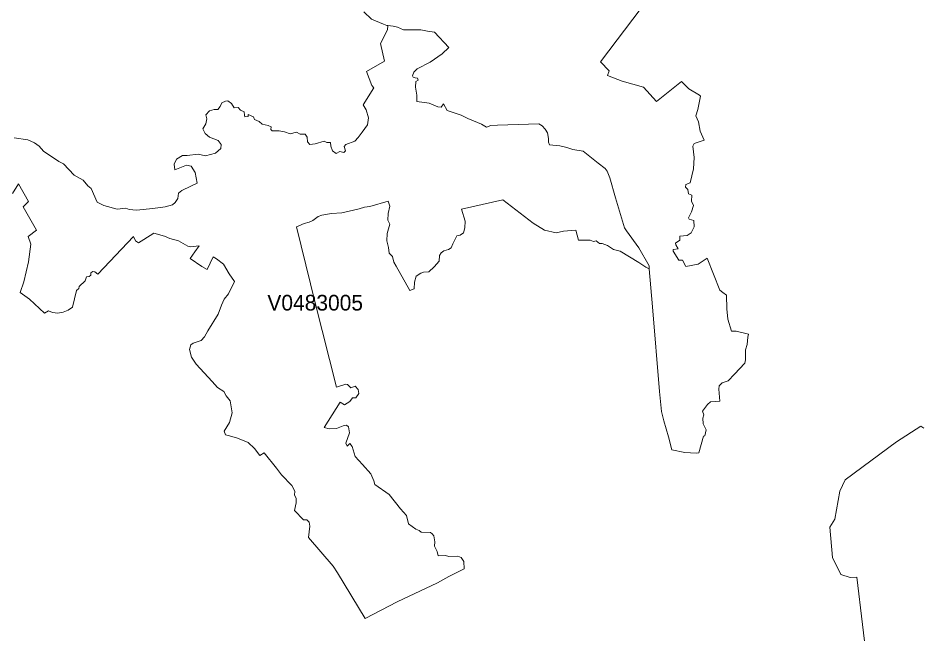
# Model space of a CAD drawing. Extents: x 369010 to 735936, y 6377141 to 6616555.
# Drawn here: x 393307 to 399077, y 6478465 to 6482389 of the extents above; entities that cross this region are included whole.
import ezdxf
from ezdxf.enums import TextEntityAlignment as Align

# ---------------------------------------------------------------- set-up
doc = ezdxf.new("R2010")
doc.units = 0
doc.header["$LTSCALE"] = 40
doc.layers.add('3', color=7, linetype='Continuous', lineweight=13)
doc.layers.add('4', color=7, linetype='Continuous')

msp = doc.modelspace()

# ---------------------------------------------------------------- linework, layer by layer
at = {"layer": '3'}
for points in [[(394667.46, 6481843.62), (394684.68, 6481817.3), (394710.66, 6481818.63), (394726.38, 6481802.9), (394748.73, 6481790.99), (394751.37, 6481771.29), (394754.02, 6481759.37), (394775.04, 6481760.7), (394773.72, 6481775.26), (394807.81, 6481759.37), (394814.43, 6481743.65), (394844.72, 6481730.41), (394864.41, 6481713.36), (394902.65, 6481704.1), (394921.02, 6481694.99), (394918.37, 6481679.11), (394927.64, 6481671.16), (394972.32, 6481669.84), (395006.42, 6481663.38), (395042, 6481651.47), (395082.55, 6481662.06), (395106.21, 6481650.14), (395137.83, 6481650.14), (395149.74, 6481630.45), (395152.23, 6481600.16), (395166.79, 6481583.11), (395202.21, 6481588.41), (395259.64, 6481605.46), (395275.53, 6481596.35), (395299.19, 6481596.35), (395301.84, 6481572.69), (395312.27, 6481543.72), (395334.61, 6481525.19), (395358.28, 6481539.75), (395384.59, 6481533.13), (395395.18, 6481543.72), (395385.92, 6481571.36), (395397.67, 6481583.11), (395454.27, 6481605.46), (395475.29, 6481627.96), (395501.6, 6481662.06), (395534.37, 6481709.23), (395542.15, 6481753.91), (395527.75, 6481803.9), (395514.51, 6481826.4), (395508.06, 6481835.51), (395575.09, 6481943.42), (395561.85, 6481959.3), (395529.08, 6482047.52), (395644.6, 6482114.05), (395618.28, 6482227.25), (395662.97, 6482314.14), (395665.95, 6482341.45), (395658.67, 6482342.28), (395637.65, 6482349.73), (395561.52, 6482382.66), (395512.86, 6482428.67)], [(395512.86, 6482428.67), (395561.52, 6482382.66), (395637.65, 6482349.73), (395658.67, 6482342.28), (395665.95, 6482341.45)], [(397280.44, 6482453), (397021.76, 6482109.08), (397077.04, 6482052.48), (397065.12, 6482023.85), (397159.79, 6481986.94), (397295.34, 6481948.71), (397377.92, 6481857.35), (397536.97, 6481984.96), (397584.47, 6481938.95), (397652.82, 6481896.74), (397657.96, 6481891.61), (397640.91, 6481806.05), (397627.83, 6481765.17), (397644.88, 6481728.43), (397655.47, 6481669.18), (397682.95, 6481611.25), (397617.24, 6481590.23), (397609.3, 6481572.36), (397618.57, 6481499.86), (397613.27, 6481428.86), (397593.57, 6481338), (397564.61, 6481328.9), (397561.96, 6481310.36), (397577.85, 6481297.29), (397583.15, 6481268.32), (397602.84, 6481260.38), (397600.19, 6481222.15), (397614.59, 6481195.01), (397601.35, 6481154.13), (397582.98, 6481116.06), (397585.63, 6481106.79), (397615.92, 6481098.85), (397617.24, 6481059.46), (397600.03, 6481021.23), (397573.88, 6481002.86), (397526.38, 6481000.21), (397526.55, 6480973.4), (397500.23, 6480953.54), (397501.55, 6480943.11), (397515.95, 6480919.44), (397484.34, 6480914.15), (397484.34, 6480903.55), (397521.25, 6480845.63), (397543.59, 6480845.63), (397563.29, 6480810.04), (397564.61, 6480804.91), (397643.56, 6480820.64), (397700.16, 6480858.87), (397782.58, 6480655.13), (397800.95, 6480639.41), (397824.62, 6480622.2), (397827.27, 6480536.8), (397833.89, 6480469.6), (397856.23, 6480394.63), (397886.52, 6480394.63), (397964.97, 6480374.27), (397959.67, 6480355.74), (397957.02, 6480309.73), (397945.27, 6480274.14), (397945.27, 6480210.92), (397941.3, 6480189.9), (397875.59, 6480118.9), (397834.88, 6480078.02), (397796.65, 6480064.94), (397778.28, 6480045.08), (397775.96, 6480024.73), (397781.26, 6479947.11), (397722.01, 6479943.13), (397703.8, 6479927.25), (397672.19, 6479884.05), (397678.81, 6479860.38), (397673.51, 6479839.36), (397674.84, 6479802.46), (397694.53, 6479764.22), (397685.26, 6479727.48), (397677.49, 6479724.83), (397647.2, 6479618.25), (397630.15, 6479615.6), (397558.98, 6479620.9), (397474.91, 6479636.62), (397454.05, 6479720.37), (397423.77, 6479821.65), (397410.69, 6479880.9), (397396.29, 6480010.33), (397352.93, 6480549.04)], [(397515.95, 6480919.44), (397501.55, 6480943.11), (397500.23, 6480953.54), (397526.55, 6480973.4), (397526.38, 6481000.21), (397573.88, 6481002.86), (397600.03, 6481021.23), (397617.24, 6481059.46), (397615.92, 6481098.85), (397585.63, 6481106.79), (397582.98, 6481116.06), (397601.35, 6481154.13), (397614.59, 6481195.01), (397600.19, 6481222.15), (397602.84, 6481260.38), (397583.15, 6481268.32), (397577.85, 6481297.29), (397561.96, 6481310.36), (397564.61, 6481328.9), (397593.57, 6481338), (397613.27, 6481428.86), (397618.57, 6481499.86), (397609.3, 6481572.36), (397617.24, 6481590.23), (397682.95, 6481611.25), (397655.47, 6481669.18), (397644.88, 6481728.43), (397627.83, 6481765.17), (397640.91, 6481806.05), (397657.96, 6481891.61), (397652.82, 6481896.74), (397584.47, 6481938.95), (397536.97, 6481984.96), (397377.92, 6481857.35), (397295.34, 6481948.71), (397159.79, 6481986.94), (397065.12, 6482023.85), (397077.04, 6482052.48), (397021.76, 6482109.08), (397280.44, 6482453)], [(395665.95, 6482341.45), (395662.97, 6482314.14), (395618.28, 6482227.25), (395644.6, 6482114.05), (395529.08, 6482047.52), (395561.85, 6481959.3), (395575.09, 6481943.42), (395508.06, 6481835.51), (395514.51, 6481826.4), (395527.75, 6481803.9), (395542.15, 6481753.91), (395534.37, 6481709.23), (395501.6, 6481662.06), (395475.29, 6481627.96), (395454.27, 6481605.46), (395397.67, 6481583.11), (395385.92, 6481571.36), (395395.18, 6481543.72), (395384.59, 6481533.13), (395358.28, 6481539.75), (395334.61, 6481525.19), (395312.27, 6481543.72), (395301.84, 6481572.69), (395299.19, 6481596.35), (395275.53, 6481596.35), (395259.64, 6481605.46), (395202.21, 6481588.41), (395166.79, 6481583.11), (395152.23, 6481600.16), (395149.74, 6481630.45), (395137.83, 6481650.14), (395106.21, 6481650.14), (395082.55, 6481662.06), (395042, 6481651.47), (395006.42, 6481663.38), (394972.32, 6481669.84), (394927.64, 6481671.16), (394918.37, 6481679.11), (394921.02, 6481694.99), (394902.65, 6481704.1), (394864.41, 6481713.36), (394844.72, 6481730.41), (394814.43, 6481743.65), (394807.81, 6481759.37), (394773.72, 6481775.26), (394775.04, 6481760.7), (394754.02, 6481759.37), (394751.37, 6481771.29), (394748.73, 6481790.99), (394726.38, 6481802.9), (394710.66, 6481818.63), (394684.68, 6481817.3), (394667.46, 6481843.62), (394643.8, 6481860.66), (394630.72, 6481859.34), (394607.05, 6481848.75), (394596.46, 6481826.4), (394580.74, 6481805.38), (394558.4, 6481805.38), (394528.11, 6481797.44), (394504.44, 6481772.45), (394511.06, 6481747.46), (394504.44, 6481714.52), (394486.07, 6481682.91), (394499.15, 6481654.11), (394526.95, 6481629.45), (394583.55, 6481608.44), (394601.92, 6481583.44), (394599.28, 6481558.45), (394566.34, 6481528.17), (394501.96, 6481511.12), (394454.63, 6481521.55), (394386.27, 6481513.77), (394355.99, 6481512.44), (394316.6, 6481490.1), (394303.36, 6481458.49), (394306, 6481422.91), (394380.98, 6481451.87), (394409.94, 6481445.25), (394436.25, 6481405.86), (394449.66, 6481336.51), (394408.95, 6481318.14), (394352.34, 6481290.5), (394330, 6481273.46), (394326.03, 6481239.2), (394308.98, 6481212.88), (394291.94, 6481198.32), (394245.93, 6481186.57), (394165.99, 6481175.97), (394063.37, 6481164.22), (394016.04, 6481169.35), (393995.02, 6481178.62), (393938.42, 6481170.68), (393853.35, 6481195.5), (393811.31, 6481216.52), (393773.41, 6481303.08), (393751.07, 6481320.13), (393722.11, 6481355.71), (393664.18, 6481387.32), (393597.15, 6481459.65)], [(395549.6, 6481188.22), (395666.61, 6481222.48), (395678.53, 6481190.87), (395667.94, 6481143.53), (395663.96, 6481101.5), (395677.2, 6481075.02), (395659.99, 6481015.93), (395657.51, 6480969.76), (395669.26, 6480927.72), (395673.23, 6480890.81), (395694.25, 6480869.79), (395703.52, 6480832.88), (395718.75, 6480807.89), (395805.47, 6480652.65), (395831.78, 6480664.4), (395834.43, 6480706.6), (395845.02, 6480744.67), (395875.31, 6480763.21), (395892.36, 6480769.66), (395926.62, 6480772.31), (395960.71, 6480803.92), (395992.32, 6480840.83), (395994.97, 6480874.92), (396005.4, 6480893.46), (396020.96, 6480904.88), (396052.57, 6480913.98), (396068.29, 6480924.57), (396078.88, 6480949.56), (396105.2, 6481000.87), (396126.22, 6481004.84), (396147.24, 6481020.73), (396156.34, 6481052.18), (396157.66, 6481094.38), (396133.99, 6481172), (396397.64, 6481231.58), (396592.28, 6481082.79), (396664.6, 6481036.78), (396739.08, 6481021.39), (396785.25, 6481030.5), (396862.71, 6481038.44), (396879.92, 6480973.89), (396954.73, 6480972.73), (396975.91, 6480964.79), (396992.96, 6480968.76), (397015.3, 6480951.55), (397031.03, 6480951.55), (397065.29, 6480939.8), (397104.68, 6480913.48), (397145.56, 6480904.22), (397265.71, 6480832.22), (397310.56, 6480800.78), (397332.24, 6480791.67), (397330.59, 6480810.87), (397265.21, 6480924.74), (397186.27, 6481033.97), (397174.35, 6481052.51), (397116.76, 6481244), (397079.85, 6481371.6), (397064.13, 6481412.48), (397050.89, 6481430.85), (397005.21, 6481464.78), (396910.54, 6481541.08), (396843.84, 6481551.34), (396807.1, 6481564.41), (396762.41, 6481575), (396695.38, 6481581.46), (396688.76, 6481597.35), (396688.76, 6481622.34), (396682.14, 6481657.92), (396667.75, 6481680.26), (396648.05, 6481701.28), (396628.19, 6481715.85), (396365.2, 6481706.58), (396322.34, 6481703.93), (396294.7, 6481694.66), (396263.09, 6481713.03), (396175.21, 6481748.29), (396133.17, 6481770.79), (396043.8, 6481800.92), (396020.13, 6481841.8), (396004.24, 6481822.1), (395983.22, 6481823.42), (395929.27, 6481845.77), (395850.49, 6481857.52), (395849.16, 6481897.07), (395841.22, 6481949.7), (395843.87, 6481985.29), (395858.27, 6481993.07), (395853.13, 6482004.98), (395839.89, 6482008.95), (395826.82, 6482011.6), (395821.36, 6482020.21), (395830.63, 6482045.2), (395851.64, 6482064.9), (395935.89, 6482108.42), (396010.86, 6482161.05), (396052.9, 6482201.77), (395962.2, 6482299.25), (395917.68, 6482305.37), (395874.32, 6482313.32)], [(395874.32, 6482313.32), (395823.01, 6482314.64), (395763.93, 6482313.32), (395725.7, 6482331.69), (395698.06, 6482338.31), (395665.95, 6482341.45)], [(395665.95, 6482341.45), (395698.06, 6482338.31), (395725.7, 6482331.69), (395763.93, 6482313.32), (395823.01, 6482314.64), (395874.32, 6482313.32), (395917.68, 6482305.37), (395962.2, 6482299.25), (396052.9, 6482201.77), (396010.86, 6482161.05), (395935.89, 6482108.42), (395851.64, 6482064.9), (395830.63, 6482045.2), (395821.36, 6482020.21), (395826.82, 6482011.6), (395839.89, 6482008.95), (395853.13, 6482004.98), (395858.27, 6481993.07), (395843.87, 6481985.29), (395841.22, 6481949.7), (395849.16, 6481897.07), (395850.49, 6481857.52), (395929.27, 6481845.77), (395983.22, 6481823.42), (396004.24, 6481822.1), (396020.13, 6481841.8), (396043.8, 6481800.92), (396133.17, 6481770.79), (396175.21, 6481748.29), (396263.09, 6481713.03), (396294.7, 6481694.66), (396322.34, 6481703.93), (396365.2, 6481706.58), (396628.19, 6481715.85), (396648.05, 6481701.28), (396667.75, 6481680.26), (396682.14, 6481657.92), (396688.76, 6481622.34), (396688.76, 6481597.35), (396695.38, 6481581.46), (396762.41, 6481575), (396807.1, 6481564.41), (396843.84, 6481551.34), (396910.54, 6481541.08), (397005.21, 6481464.78), (397050.89, 6481430.85), (397064.13, 6481412.48), (397079.85, 6481371.6), (397116.76, 6481244), (397174.35, 6481052.51), (397186.27, 6481033.97), (397265.21, 6480924.74), (397330.59, 6480810.87), (397332.24, 6480791.67), (397352.93, 6480549.04), (397396.29, 6480010.33), (397410.69, 6479880.9), (397423.77, 6479821.65), (397454.05, 6479720.37), (397474.91, 6479636.62), (397558.98, 6479620.9), (397630.15, 6479615.6), (397647.2, 6479618.25), (397677.49, 6479724.83), (397685.26, 6479727.48), (397694.53, 6479764.22), (397674.84, 6479802.46), (397673.51, 6479839.36), (397678.81, 6479860.38), (397672.19, 6479884.05), (397703.8, 6479927.25), (397722.01, 6479943.13), (397781.26, 6479947.11), (397775.96, 6480024.73), (397778.28, 6480045.08), (397796.65, 6480064.94), (397834.88, 6480078.02), (397875.59, 6480118.9), (397941.3, 6480189.9), (397945.27, 6480210.92), (397945.27, 6480274.14), (397957.02, 6480309.73), (397959.67, 6480355.74), (397964.97, 6480374.27), (397886.52, 6480394.63), (397856.23, 6480394.63), (397833.89, 6480469.6), (397827.27, 6480536.8), (397824.62, 6480622.2), (397800.95, 6480639.41), (397782.58, 6480655.13), (397700.16, 6480858.87), (397643.56, 6480820.64), (397564.61, 6480804.91), (397563.29, 6480810.04), (397543.59, 6480845.63), (397521.25, 6480845.63), (397484.34, 6480903.55), (397484.34, 6480914.15), (397515.95, 6480919.44)], [(393283.35, 6481625.15), (393368.75, 6481613.4), (393410.96, 6481594.86), (393440.75, 6481572.85), (393469.71, 6481541.24), (393567.03, 6481475.54), (393597.15, 6481459.65), (393664.18, 6481387.32), (393722.11, 6481355.71), (393751.07, 6481320.13), (393773.41, 6481303.08), (393811.31, 6481216.52), (393853.35, 6481195.5), (393938.42, 6481170.68), (393995.02, 6481178.62), (394016.04, 6481169.35), (394063.37, 6481164.22), (394165.99, 6481175.97), (394245.93, 6481186.57), (394291.94, 6481198.32), (394308.98, 6481212.88), (394326.03, 6481239.2), (394330, 6481273.46), (394352.34, 6481290.5), (394408.95, 6481318.14), (394449.66, 6481336.51), (394436.25, 6481405.86), (394409.94, 6481445.25), (394380.98, 6481451.87), (394306, 6481422.91), (394303.36, 6481458.49), (394316.6, 6481490.1), (394355.99, 6481512.44), (394386.27, 6481513.77), (394454.63, 6481521.55), (394501.96, 6481511.12), (394566.34, 6481528.17), (394599.28, 6481558.45), (394601.92, 6481583.44), (394583.55, 6481608.44), (394526.95, 6481629.45), (394499.15, 6481654.11), (394486.07, 6481682.91), (394504.44, 6481714.52), (394511.06, 6481747.46), (394504.44, 6481772.45), (394528.11, 6481797.44), (394558.4, 6481805.38), (394580.74, 6481805.38), (394596.46, 6481826.4), (394607.05, 6481848.75), (394630.72, 6481859.34), (394643.8, 6481860.66), (394667.46, 6481843.62)], [(393597.15, 6481459.65), (393567.03, 6481475.54), (393469.71, 6481541.24), (393440.75, 6481572.85), (393410.96, 6481594.86), (393368.75, 6481613.4), (393283.35, 6481625.15)], [(393381, 6480597.7), (393320.59, 6480639.91), (393342.94, 6480708.26), (393373.22, 6480836.03), (393387.62, 6480949.07), (393370.57, 6480996.57), (393424.86, 6481038.11), (393340.62, 6481185.57), (393373.55, 6481219.83), (393310.5, 6481332.54), (393272.43, 6481270.81)], [(393272.43, 6481270.81), (393310.5, 6481332.54), (393373.55, 6481219.83), (393340.62, 6481185.57), (393424.86, 6481038.11), (393370.57, 6480996.57), (393387.62, 6480949.07), (393373.22, 6480836.03), (393342.94, 6480708.26), (393320.59, 6480639.91), (393381, 6480597.7), (393475.67, 6480509.49), (393500.66, 6480524.05), (393526.98, 6480513.46), (393561.24, 6480508.16), (393594, 6480514.78), (393626.94, 6480526.7), (393654.58, 6480547.72), (393679.57, 6480652.98), (393695.29, 6480666.22), (393696.62, 6480679.3), (393734.85, 6480713.56), (393743.95, 6480739.87), (393761, 6480742.52), (393770.27, 6480750.46), (393770.1, 6480765.52), (393783.18, 6480774.79), (393797.57, 6480772.14), (393816.11, 6480756.42), (394043.51, 6480997.23), (394056.75, 6480969.59), (394075.79, 6480956.85), (394110.05, 6480978.03), (394173.1, 6481018.74), (394240.13, 6480999.05), (394275.72, 6480984.49), (394330.99, 6480968.76), (394388.76, 6480934.5), (394407.29, 6480931.85), (394462.4, 6480937.15), (394434.77, 6480900.24), (394404.64, 6480856.88), (394478.29, 6480805.58), (394513.71, 6480785.88), (394551.94, 6480867.47), (394572.96, 6480855.56), (394617.65, 6480821.3), (394654.22, 6480760.06), (394687.16, 6480710.08), (394649.09, 6480632.46), (394621.45, 6480596.87), (394604.24, 6480558.64), (394583.22, 6480502.21), (394516.19, 6480396.78), (394496.5, 6480357.39), (394475.48, 6480335.05), (394422.85, 6480316.51), (394408.28, 6480306.91)], [(397352.93, 6480549.04), (397332.24, 6480791.67), (397310.56, 6480800.78), (397265.71, 6480832.22), (397145.56, 6480904.22), (397104.68, 6480913.48), (397065.29, 6480939.8), (397031.03, 6480951.55), (397015.3, 6480951.55), (396992.96, 6480968.76), (396975.91, 6480964.79), (396954.73, 6480972.73), (396879.92, 6480973.89), (396862.71, 6481038.44), (396785.25, 6481030.5), (396739.08, 6481021.39), (396664.6, 6481036.78), (396592.28, 6481082.79), (396397.64, 6481231.58), (396133.99, 6481172), (396157.66, 6481094.38), (396156.34, 6481052.18), (396147.24, 6481020.73), (396126.22, 6481004.84), (396105.2, 6481000.87), (396078.88, 6480949.56), (396068.29, 6480924.57), (396052.57, 6480913.98), (396020.96, 6480904.88), (396005.4, 6480893.46), (395994.97, 6480874.92), (395992.32, 6480840.83), (395960.71, 6480803.92), (395926.62, 6480772.31), (395892.36, 6480769.66), (395875.31, 6480763.21), (395845.02, 6480744.67), (395834.43, 6480706.6), (395831.78, 6480664.4), (395805.47, 6480652.65), (395718.75, 6480807.89), (395703.52, 6480832.88), (395694.25, 6480869.79), (395673.23, 6480890.81), (395669.26, 6480927.72), (395657.51, 6480969.76), (395659.99, 6481015.93), (395677.2, 6481075.02), (395663.96, 6481101.5), (395667.94, 6481143.53), (395678.53, 6481190.87), (395666.61, 6481222.48), (395549.6, 6481188.22), (395515.34, 6481183.09), (395482.57, 6481173.82), (395418.19, 6481159.26), (395370.69, 6481147.51), (395304.99, 6481143.53), (395245.07, 6481132.61), (395221.41, 6481123.51), (395185.82, 6481099.84), (395163.48, 6481089.25), (395130.71, 6481079.98), (395097.77, 6481064.26), (395082.05, 6481057.64), (395201.71, 6480575.19), (395337.26, 6480037.8), (395397.5, 6480056.84), (395408.09, 6480052.86), (395429.11, 6480033.17), (395456.75, 6480043.59), (395476.45, 6480022.58), (395480.42, 6479997.58), (395461.88, 6479969.95), (395439.54, 6479969.95), (395422.49, 6479944.95), (395388.23, 6479923.94), (395360.76, 6479940.98), (395258.15, 6479780.94), (395291.08, 6479771.84), (395338.42, 6479774.49), (395380.46, 6479790.21), (395401.47, 6479794.18), (395414.55, 6479784.91), (395421.17, 6479746.85), (395396.18, 6479679.65), (395405.45, 6479661.28), (395422.49, 6479677), (395437.06, 6479658.63), (395456.75, 6479594.09), (395504.09, 6479544.1), (395556.72, 6479484.85), (395576.25, 6479440.66), (395582.87, 6479415.67), (395673.56, 6479353.77), (395745.56, 6479260.93), (395783.79, 6479220.05), (395796.86, 6479166.09), (395844.2, 6479131.83), (395863.89, 6479122.73)], [(394408.28, 6480306.91), (394400.51, 6480276.62), (394412.26, 6480227.97), (394442.54, 6480183.11), (394544.83, 6480072.89), (394577.76, 6480034.66), (394619.8, 6480008.34), (394634.2, 6479980.7), (394659.19, 6479950.58), (394672.43, 6479874.12), (394656.38, 6479811.56), (394622.28, 6479756.28), (394630.23, 6479733.94), (394655.22, 6479725.99), (394706.36, 6479712.92), (394774.88, 6479685.28), (394815.59, 6479647.05), (394848.53, 6479601.04), (394876, 6479618.08), (394954.61, 6479521.26), (394987.55, 6479479.23), (395053.25, 6479410.71), (395071.62, 6479373.8), (395068.98, 6479348.81), (395079.57, 6479330.44), (395079.57, 6479300.15), (395068.81, 6479251.99), (395127.9, 6479191.41), (395148.91, 6479191.41), (395163.48, 6479177.02), (395167.29, 6479150.7), (395158.18, 6479079.53), (395315.91, 6478895.33), (395343.22, 6478853.62), (395520.64, 6478562.83), (395724.54, 6478668.09), (395982.06, 6478790.07), (396053.06, 6478830.78), (396151.54, 6478879.44), (396149.06, 6478926.94), (396131.84, 6478950.61), (396112.15, 6478959.87), (396054.39, 6478958.55), (396033.2, 6478963.68), (395985.87, 6478961.03), (395979.41, 6478990), (395962.2, 6479024.26), (395963.86, 6479051.56), (395957.24, 6479089.8), (395948.13, 6479101.55), (395936.22, 6479110.81), (395878.46, 6479113.46), (395863.89, 6479122.73), (395844.2, 6479131.83), (395796.86, 6479166.09), (395783.79, 6479220.05), (395745.56, 6479260.93), (395673.56, 6479353.77), (395582.87, 6479415.67), (395576.25, 6479440.66), (395556.72, 6479484.85), (395504.09, 6479544.1), (395456.75, 6479594.09), (395437.06, 6479658.63), (395422.49, 6479677), (395405.45, 6479661.28), (395396.18, 6479679.65), (395421.17, 6479746.85), (395414.55, 6479784.91), (395401.47, 6479794.18), (395380.46, 6479790.21), (395338.42, 6479774.49), (395291.08, 6479771.84), (395258.15, 6479780.94), (395360.76, 6479940.98), (395388.23, 6479923.94), (395422.49, 6479944.95), (395439.54, 6479969.95), (395461.88, 6479969.95), (395480.42, 6479997.58), (395476.45, 6480022.58), (395456.75, 6480043.59), (395429.11, 6480033.17), (395408.09, 6480052.86), (395397.5, 6480056.84), (395337.26, 6480037.8), (395201.71, 6480575.19), (395082.05, 6481057.64), (395097.77, 6481064.26), (395130.71, 6481079.98), (395163.48, 6481089.25), (395185.82, 6481099.84), (395221.41, 6481123.51), (395245.07, 6481132.61), (395304.99, 6481143.53), (395370.69, 6481147.51), (395418.19, 6481159.26), (395482.57, 6481173.82), (395515.34, 6481183.09), (395549.6, 6481188.22)], [(395863.89, 6479122.73), (395878.46, 6479113.46), (395936.22, 6479110.81), (395948.13, 6479101.55), (395957.24, 6479089.8), (395963.86, 6479051.56), (395962.2, 6479024.26), (395979.41, 6478990), (395985.87, 6478961.03), (396033.2, 6478963.68), (396054.39, 6478958.55), (396112.15, 6478959.87), (396131.84, 6478950.61), (396149.06, 6478926.94), (396151.54, 6478879.44), (396053.06, 6478830.78), (395982.06, 6478790.07), (395724.54, 6478668.09), (395520.64, 6478562.83), (395343.22, 6478853.62), (395315.91, 6478895.33), (395158.18, 6479079.53), (395167.29, 6479150.7), (395163.48, 6479177.02), (395148.91, 6479191.41), (395127.9, 6479191.41), (395068.81, 6479251.99), (395079.57, 6479300.15), (395079.57, 6479330.44), (395068.98, 6479348.81), (395071.62, 6479373.8), (395053.25, 6479410.71), (394987.55, 6479479.23), (394954.61, 6479521.26), (394876, 6479618.08), (394848.53, 6479601.04), (394815.59, 6479647.05), (394774.88, 6479685.28), (394706.36, 6479712.92), (394655.22, 6479725.99), (394630.23, 6479733.94), (394622.28, 6479756.28), (394656.38, 6479811.56), (394672.43, 6479874.12), (394659.19, 6479950.58), (394634.2, 6479980.7), (394619.8, 6480008.34), (394577.76, 6480034.66), (394544.83, 6480072.89), (394442.54, 6480183.11), (394412.26, 6480227.97), (394400.51, 6480276.62), (394408.28, 6480306.91), (394422.85, 6480316.51), (394475.48, 6480335.05), (394496.5, 6480357.39), (394516.19, 6480396.78), (394583.22, 6480502.21), (394604.24, 6480558.64), (394621.45, 6480596.87), (394649.09, 6480632.46), (394687.16, 6480710.08), (394654.22, 6480760.06), (394617.65, 6480821.3), (394572.96, 6480855.56), (394551.94, 6480867.47), (394513.71, 6480785.88), (394478.29, 6480805.58), (394404.64, 6480856.88), (394434.77, 6480900.24), (394462.4, 6480937.15), (394407.29, 6480931.85), (394388.76, 6480934.5), (394330.99, 6480968.76), (394275.72, 6480984.49), (394240.13, 6480999.05), (394173.1, 6481018.74), (394110.05, 6480978.03), (394075.79, 6480956.85), (394056.75, 6480969.59), (394043.51, 6480997.23), (393816.11, 6480756.42), (393797.57, 6480772.14), (393783.18, 6480774.79), (393770.1, 6480765.52), (393770.27, 6480750.46), (393761, 6480742.52), (393743.95, 6480739.87), (393734.85, 6480713.56), (393696.62, 6480679.3), (393695.29, 6480666.22), (393679.57, 6480652.98), (393654.58, 6480547.72), (393626.94, 6480526.7), (393594, 6480514.78), (393561.24, 6480508.16), (393526.98, 6480513.46), (393500.66, 6480524.05), (393475.67, 6480509.49), (393381, 6480597.7)], [(398727.28, 6478223.88), (398654.79, 6478825.98), (398612.75, 6478824.66), (398553.66, 6478843.03), (398501.03, 6478952.26), (398483.99, 6479145.74), (398514.27, 6479196.38), (398547.21, 6479373.97), (398581.3, 6479446.46), (398907.35, 6479689.58), (399063.42, 6479789.22), (399081.79, 6479774.82)], [(399081.79, 6479774.82), (399063.42, 6479789.22), (398907.35, 6479689.58), (398581.3, 6479446.46), (398547.21, 6479373.97), (398514.27, 6479196.38), (398483.99, 6479145.74), (398501.03, 6478952.26), (398553.66, 6478843.03), (398612.75, 6478824.66), (398654.79, 6478825.98), (398727.28, 6478223.88), (398743, 6478079.06), (398695.17, 6477908.26), (398968.58, 6477819.22), (399137.56, 6477761.29)]]:
    msp.add_lwpolyline(points, dxfattribs=at)

# ---------------------------------------------------------------- texts
at = {"layer": '4'}
msp.add_text('V0483005', height=100, dxfattribs=at).set_placement((395201.71, 6480525.19), align=Align.CENTER)

doc.saveas('drawing.dxf')
